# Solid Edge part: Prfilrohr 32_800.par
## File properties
Username: ahadarics
Dokumentum tartalom típus: 0
Author: ahadarics
Last saved by: ahadarics
Revision: 91
Sűrűség: 0,000 kg/m^3
Pontosság: 0,990
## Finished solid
Body 1: solid body, 179 faces, 531 edges, 354 vertices.
  Faces by surface: cylinder 109, plane 70
  Edges by curve: line 313, circle 218
Bounding box of the edges (mm): 44.254 x 44.254 x 841.000, from (-22.1268, -22.1268, -13) to (22.1268, 22.1268, 828).
Cylindrical faces by radius (mm): R0.1 x16, R0.2 x30, R0.5 x32, R1 x6, R2.7 x8, R4.5 x4, R4.7 x4, R16 x1, R18 x8
Planar faces by outward normal: +x 6, +y 6, +z 1, -x 4, -y 4, -z 1, oblique 48
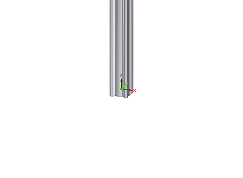
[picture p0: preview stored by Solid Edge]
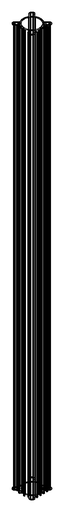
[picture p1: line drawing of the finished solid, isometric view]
